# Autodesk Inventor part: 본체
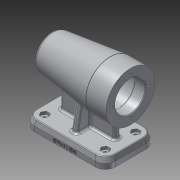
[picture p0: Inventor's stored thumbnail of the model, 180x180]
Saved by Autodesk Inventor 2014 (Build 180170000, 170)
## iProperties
Created: 2017-01
Part Number: 본체
Material: 알루미늄 6061
Document SubType Name: Modeling
Designer: owner
Density: 2.71 g/cm^3
Appearance: 알루미늄 - 평지
Mass: 795.321 g
Surface Area: 661.924 cm^2
Volume: 293.476 cm^3
Author: owner
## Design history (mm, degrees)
sketch "스케치1"
  geometry: L1 (-56, 0)-(56, 0); L2 (56, 21)-(56, 34); L3 (56, 34)-(28, 34); L4 (28, 34)-(-52.27, 24.144); L5 (56, 21)-(41, 21); L6 (41, 21)-(41, 24); L7 (41, 24)-(-13, 24); L8 (-13, 24)-(-13, 21); L9 (-13, 21)-(-25, 21); L10 (-25, 21)-(-25, 17.5); L11 (-25, 17.5)-(-43, 17.5); L12 (-43, 17.5)-(-43, 16); L13 (-43, 16)-(-47, 16); L14 (-47, 16)-(-47, 10.5); L15 (-47, 10.5)-(-50, 10.5); L16 (-50, 10.5)-(-50, 0); A1 r 80 centre (24, 0) between (-52.27, 24.144) and (-56, 0); 2 further points
  constraints: 32 end point, 9 parallel, 4 perpendicular, 2 horizontal alignment, 2 point on circle, 1 centre point, 1 coincident, 1 collinear, 1 horizontal, 1 midpoint, 1 point on line, 1 vertical alignment
  dimensions: "d0" = 112 distance of L1.start L1.end; "d2" = 68 diameter of L3 L1; "d3" = 42 diameter of L5 L1; "d4" = 48 diameter of L7 L1; "d5" = 42 diameter of L9 L1; "d6" = 35 diameter of L11 L1; "d7" = 32 diameter of L13 L1; "d8" = 21 diameter of L15 L1; "d9" = 28 distance of L2.end L3.end; "d10" = 80 radius of A1; "d11" = 15 distance of L2.start L5.end; "d12" = 54 distance of L6.end L7.end; "d13" = 12 distance of L8.end L9.end; "d14" = 18 distance of L10.end L11.end; "d15" = 4 distance of L12.end L13.end; "d16" = 3 distance of L14.end L15.end; "d17" = 7 deg angle of L4 L3
revolve "회전1" sketch "스케치1" stored, may be unused: angle "d18" = 90 deg
sketch "스케치2"
  geometry: C1 r 34 at (0, 0) reference; 1 further point
  constraints: 1 vertical alignment
  dimensions: "d19" = 26 distance of C1.centre point (0, 26)
hole "구멍1" sketch "스케치2" at (0, 26) diameter "d20" = 3.242; stored, may be unused: countersink angle "d24" = 90 deg, drill point angle "d26" = 118 deg; dims "d21" = 8, "d22" = 4, "d23" = 2, "d25" = 11
fillet "모깎기1" dims "d30" = 3, "d31" = 0.3
chamfer "모따기1" distance "d32" = 1; stored, may be unused: second distance "d33" = 2, angle "d34" = 45 deg
node "작업 평면3"
sketch "스케치5"
  geometry: L1 (56, -35)-(-56, -35); L2 (-56, -35)-(-56, 35); L3 (-56, 35)-(56, 35); L4 (56, 35)-(56, -35); L5 (56, -35)-(-56, 35); L6 (-56, -35)-(56, 35); 1 further point
  constraints: 12 end point, 2 midpoint, 2 parallel, 1 horizontal, 1 perpendicular
  dimensions: "d45" = 112 distance of L2.end L3.end; "d46" = 70 distance of L1.end L2.end
extrude "돌출3" join sketch "스케치5" distance "d47" = 7; taper "d48" = -15 deg
fillet "모깎기2" dims "d49" = 14, "d50" = 1
sketch "스케치6"
  geometry: L1 (42.477, 35)-(-42.477, 35) reference; L2 (-56, 21.477)-(-56, -21.477) reference; L3 (-42.477, -35)-(42.477, -35) reference; L4 (56, -21.477)-(56, 21.477) reference; L5 (56, 35)-(-56, 35); L6 (-56, 35)-(-56, -35); L7 (-56, -35)-(56, -35); L8 (56, -35)-(56, 35); L9 (56, 35)-(-56, -35); L10 (-56, 35)-(56, -35); 5 further points; 4 other entities
  constraints: 12 end point, 2 midpoint, 2 parallel, 1 horizontal, 1 perpendicular, 4 other
  dimensions: "d51" = 112 distance of L6.end L7.end; "d52" = 70 distance of L7.end L5.start
extrude "돌출4" join sketch "스케치6" distance "d53" = 7; taper "d54" = 0 deg
sketch "스케치10"
  geometry: L1 (-47.774, -21)-(-44.887, -16); L2 (-44.887, -16)-(-39.113, -16); L3 (-39.113, -16)-(-36.226, -21); L4 (-36.226, -21)-(-39.113, -26); L5 (-39.113, -26)-(-44.887, -26); L6 (-44.887, -26)-(-47.774, -21); L7 (-56, -21.477)-(-56, 21.477) reference; L8 (42.477, -35)-(-42.477, -35) reference; 6 further points; 1 other entity
  constraints: 12 end point, 1 coincident, 1 horizontal alignment, 14 other
  dimensions: "d115" = 5 distance from line of L5 point (-42, -21); "d123" = 14 distance from line of L7 point (-42, -21); "d124" = 14 distance from line of L8 point (-42, -21)
extrude "돌출5" cut sketch "스케치10" distance "d60" = 4; taper "d61" = 0 deg
fillet "모깎기3" dims "d71" = 3
sketch "스케치12"
  geometry: L1 (-28, -34)-(-56, -34) reference; L2 (50.331, -24.382)-(-28, -34) reference; L3 (-53.357, -60)-(-40.8, -60) reference; L4 (-40.8, -60)-(40.8, -60) reference; L5 (40.8, -60)-(53.357, -60) reference; 1 further point
node "작업 평면4"
sketch "스케치13"
  geometry: L1 (60, 19.8)-(60, -19.8) reference; L2 (60, -32.357)-(60, -19.8) reference; L3 (60, 19.8)-(60, 32.357) reference; L4 (67, -35)-(74, -35) reference; L5 (67, 35)-(74, 35) reference; L6 (60, -4)-(33.764, -4); L7 (33.764, 4)-(60, 4); A1 r 34 centre (0, 0) between (29.118, -17.555) and (29.118, 17.555) reference; 3 further points
  constraints: 4 end point, 4 point on circle, 4 point on line, 1 parallel, 1 perpendicular
  dimensions: "d89" = 4 vertical distance of L6.end point (0, 0); "d90" = 4 vertical distance of point (0, 0) L7.end
extrude "돌출6" join sketch "스케치13" distance "d79" = 10; taper "d80" = 0 deg
sketch "스케치14"
  geometry: L1 (-28, -60)-(-28, -29.118) reference; L2 (50.331, -24.382)-(-28, -34) reference; L3 (40.8, -60)-(53.357, -60) reference; L4 (-40.8, -60)-(40.8, -60) reference; L5 (38, -60)-(38, -25.896); L6 (56, -67)-(56, -74) reference; 2 further points
  constraints: 2 end point, 2 point on line, 1 perpendicular
  dimensions: "d81" = 18 distance from line of L6 L5.start
feature "리브1" sketch "스케치14" dims "d82" = 1, "d83" = 8, "d84" = 0, "d85" = 0, "d86" = 1, "d87" = 1
sketch "스케치15"
  geometry: L1 (19.8, -60)-(-19.8, -60) reference; L2 (19.8, -60)-(32.357, -60) reference; L3 (-32.357, -60)-(-19.8, -60) reference; L4 (4, -60)-(4, -33.764) reference; L5 (-4, -33.764)-(-4, -60) reference; L6 (4, -33.764)-(4, -25.585) reference; L7 (-4, -25.585)-(-4, -33.764) reference; L8 (4, -33.764)-(4, -25.585) reference; L9 (-4, -25.585)-(-4, -33.764) reference; L10 (23, -60)-(15.708, -18.648); L11 (-15.708, -18.648)-(-23, -60); L12 (35, -67)-(35, -74) reference; L13 (-35, -67)-(-35, -74) reference; L14 (4, -60)-(-4, -60) reference; L15 (4, -60)-(4, -33.764) reference; L16 (-4, -33.764)-(-4, -60) reference; L17 (4, -33.764)-(4, -25.585) reference; L18 (4, -60)-(4, -33.764) reference; L19 (4, -25.585)-(4, -60) reference; L20 (-4, -25.585)-(-4, -33.764) reference; L21 (-4, -60)-(-4, -25.585) reference; L22 (-4, -33.764)-(-4, -60) reference; C1 r 22 at (0, 0) reference; C2 r 1.621 at (0, -26) reference; C3 r 1.621 at (26, 0) reference; C4 r 1.621 at (0, 26) reference; C5 r 1.621 at (-26, 0) reference; C6 r 34 at (0, 0) reference; C7 r 24 at (0, 0) reference; C8 r 24 at (0, 0) reference; A1 r 24.382 centre (0, 0) between (15.708, -18.648) and (-15.708, -18.648) reference; A2 r 34 centre (0, 0) between (4, -33.764) and (-4, -33.764) reference; A3 r 25.896 centre (0, 0) between (-4, -25.585) and (4, -25.585) reference; A4 r 34 centre (0, 0) between (-4, -33.764) and (4, -33.764) reference; A5 r 34 centre (0, 0) between (4, -33.764) and (-4, -33.764) reference; 1 further point
  constraints: 4 end point, 2 point on circle, 2 point on line
  dimensions: "d91" = 100 deg angle of L10 L2; "d92" = 100 deg angle of L3 L11; "d93" = 12 distance from line of L12 L10.start; "d94" = 12 distance from line of L13 L11.end
  node "투영된 루프2"
  node "투영된 루프3"
  node "투영된 루프4"
  node "투영된 루프5"
  node "투영된 루프6"
  node "투영된 루프7"
feature "리브2" dims "d95" = 1, "d96" = 8, "d97" = 0, "d98" = 0, "d99" = 1, "d100" = 1
feature "리브3" dims "d101" = 1, "d102" = 8, "d103" = 0, "d104" = 0, "d105" = 1, "d106" = 1
fillet "모깎기4" dims "d107" = 3
sketch "스케치16"
  geometry: L1 (98.477, 7)-(98.477, 0) reference; L2 (84.954, 0)-(98.477, 0) reference; 2 further points
  constraints: 1 other
  dimensions: "d108" = 56 distance from line of L1 point (42.477, 4); "d109" = 4 distance from line of L2 point (42.477, 4)
feature "엠보싱1" sketch "스케치16" dims "d110" = 0.5, "d111" = 0
fillet "모깎기5" dims "d112" = 3
hole "구멍3" sketch "스케치10" diameter "d116" = 5; stored, may be unused: countersink angle "d120" = 90 deg, drill point angle "d122" = 0 deg; dims "d117" = 8, "d118" = 10, "d119" = 4, "d121" = 11
node "솔리드1"
pattern_circular "원형 패턴1" dims angle "d28" = 360 deg
mirror "대칭3"
mirror "대칭4"
other parameters: "d44" = -67, "d74" = -28
